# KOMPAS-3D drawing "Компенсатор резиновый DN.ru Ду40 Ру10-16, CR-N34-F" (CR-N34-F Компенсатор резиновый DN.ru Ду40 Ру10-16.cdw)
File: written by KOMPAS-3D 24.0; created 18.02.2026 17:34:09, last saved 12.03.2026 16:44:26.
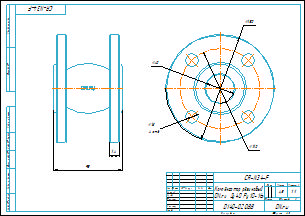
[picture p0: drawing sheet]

Document properties: Типовые: Типовые; Автор: DN.RU; Форматы листов документа: A3; Полное имя файла: CR-N34-F Компенсатор резиновый DN.ru Ду40 Ру10-16.m3d; Масса: 4.5; Наименование: Компенсатор резиновый DN.ru Ду40 Ру10-16; Количество листов документа: 1; Комментарий: D140-02088; Примечание: D140-02088

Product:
- Body: Твердое тело2  | qty 1
    Масса: 4.436857
- Part/product: Компенсатор резиновый DN.ru Ду40 Ру10-16  | designation CR-N34-F
    Масса: 4.5
    Раздел спецификации: Прочие изделия
    Комментарий: D140-02088
    Примечание: D140-02088
    additional columns: Типовые

Views: Вид 1, Спереди, Проекционный вид 2
Referenced files in E:\Работа\Зайцев\CR-N34-F Компенсатор резиновый DN.ru ДУ25-300 Ру10-16\DN40_PN10-16\: CR-N34-F Компенсатор резиновый DN.ru Ду40 Ру10-16.m3d
Referenced files in E:\Работа\Зайцев\Для компаса\: чертеж DN.ru А3.cdt
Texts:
  CR-N34-F
  чертеж DN.ru А3.cdt
  Компенсатор резиновый
  DN.ru Ду40 Ру10-16
  Твердое тело2
  Компенсатор резиновый DN.ru Ду40 Ру10-16
  CR-N34-F Компенсатор резиновый DN.ru Ду40 Ру10-16
Dimensions and other numbers on the sheet: 0; 3; 2; 4; 95; 14; 150; 110; 40; 18; 4 отв.; 1:1; 1; 4,5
